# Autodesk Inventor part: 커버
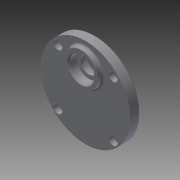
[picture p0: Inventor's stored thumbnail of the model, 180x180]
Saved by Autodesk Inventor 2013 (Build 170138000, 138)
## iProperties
Created: 2015-07
Part Number: 커버
Material: 일반
Document SubType Name: Modeling
Designer: user
Density: 1 g/cm^3
Author: user
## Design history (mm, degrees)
sketch "스케치1"
  geometry: C1 r 40 at (0, 0); 1 further point
  constraints: 1 centre point, 1 coincident
  dimensions: "d0" = 80 diameter of C1
extrude "돌출1" new body sketch "스케치1" distance "d1" = 9; taper "d2" = 0 deg
sketch "스케치2"
  geometry: C1 r 40 at (0, 0) reference; C2 r 14 at (0, 11); C3 r 14 at (0, -20)
  constraints: 2 centre point
  dimensions: "d5" = 28 diameter of C2; "d6" = 28 diameter of C3; "d7" = 11 distance of C1.centre C2.centre; "d8" = 20 distance of C1.centre C3.centre; "d9" = 31 distance of C2.centre C3.centre
extrude "돌출2" join sketch "스케치2" distance "d10" = 3; taper "d11" = 0 deg
sketch "스케치3"
  geometry: C1 r 40 at (0, 0) reference; C2 r 15 at (0, 20)
  constraints: 1 centre point
  dimensions: "d13" = 30 diameter of C2; "d14" = 20 distance of C2.centre C1.centre
extrude "돌출3" join sketch "스케치3" distance "d15" = 4; taper "d16" = 0 deg
sketch "스케치4"
  geometry: C1 r 15 at (0, 0) reference; C2 r 11 at (0, 0); 1 further point
  constraints: 1 centre point, 1 coincident
  dimensions: "d17" = 22 diameter of C2
extrude "돌출4" cut sketch "스케치4" distance "d18" = 7; taper "d19" = 0 deg
sketch "스케치5"
  geometry: C1 r 11 at (0, 0) reference; C2 r 7.5 at (0, 0); 1 further point
  constraints: 1 centre point, 1 coincident
  dimensions: "d20" = 15 diameter of C2
extrude "돌출5" cut sketch "스케치5" distance "d21" = 2; taper "d22" = 0 deg
sketch "스케치6"
  geometry: C1 r 7.5 at (0, 0) reference; C2 r 11 at (0, 0); 1 further point
  constraints: 1 centre point, 1 coincident
  dimensions: "d23" = 22 diameter of C2
extrude "돌출6" cut sketch "스케치6" distance "d24" = 7; taper "d25" = 0 deg
sketch "스케치7"
  geometry: C1 r 14 at (0, 0) reference; C2 r 11 at (0, 0); 1 further point
  constraints: 1 centre point, 1 coincident
  dimensions: "d26" = 22 diameter of C2
extrude "돌출7" cut sketch "스케치7" distance "d27" = 7; taper "d28" = 0 deg
sketch "스케치8"
  geometry: C1 r 9 at (0, 0); 2 further points
  constraints: 1 centre point, 1 coincident, 1 vertical alignment
  dimensions: "d29" = 18 diameter of C1
extrude "돌출8" cut sketch "스케치8" distance "d30" = 1; taper "d31" = 0 deg
sketch "스케치9"
  geometry: C1 r 15 at (0, 20) reference; C2 r 40 at (0, 0) reference; C3 r 4 at (24.749, 24.749)
  constraints: 1 centre point
  dimensions: "d37" = 8 diameter of C3; "d39" = 25.20021 distance of C3.centre C1.centre; "d40" = 35 distance of C3.centre C2.centre
extrude "돌출9" cut sketch "스케치9" distance "d41" = 4.4; taper "d42" = 0 deg
sketch "스케치10"
  geometry: C1 r 4 at (0, 0) reference; C2 r 2.25 at (0, 0); 1 further point
  constraints: 1 centre point, 1 coincident
  dimensions: "d43" = 4.5 diameter of C2
extrude "돌출10" cut sketch "스케치10" stored distance "d44" = 4.4; taper "d45" = 0 deg
chamfer "모따기1" distance "d50" = 1; stored, may be unused: second distance "d51" = 2, angle "d52" = 45 deg
fillet "모깎기2" dims "d53" = 2
fillet "모깎기3" dims "d54" = 0.3
fillet "모깎기4" dims "d55" = 2
chamfer "모따기2" distance "d56" = 1; stored, may be unused: second distance "d57" = 2, angle "d58" = 45 deg
node "솔리드1"
pattern_circular "원형 패턴1" dims angle "d47" = 360 deg
other parameters: "d35" = 45 deg
